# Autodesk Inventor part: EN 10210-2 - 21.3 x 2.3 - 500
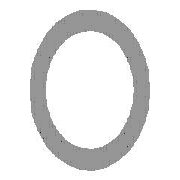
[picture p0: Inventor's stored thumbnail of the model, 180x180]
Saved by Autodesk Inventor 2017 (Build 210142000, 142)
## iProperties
Created: 2016-02
Part Number: EN 10210-2 - 21.3 x 2.3 - 500
Material: Steel, Mild
Description: Pipe
Document SubType Name: Modeling
Standard: DIN
Designer: iusti
Standard Revision: 2006-07
Standards Organization: DIN
Language: en-US
Size Designation: 21.3 x 2.3
Categories: <MemberInstance><Categories><Category DisplayName="Structural Shapes" InternalName="089c4875-fa83-4c05-b084-43b9cc11f5ed" Mnemonic="GRDR"><CategoryParameter Dis
Stock Number: 21.3 x 2.3
Density: 7.85 g/cm^3
Appearance: Semi-Polished
_CCFamilyMember: 1
_CCFamilyDisplayName: DIN EN 10210-2 - Pipe
_FrameMemberDoc: Frame Member File
_Version: 15.0.0
_GetPNFromCC: 1
IsCustomPart: 1
Author: iusti
G_L: 500.000 mm
G_W: 21.300 mm
G_H: 21.300 mm
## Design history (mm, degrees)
node "Start plane"
node "End plane"
sketch "Sketch"
  geometry: C1 r 8.35 at (0, 0); C2 r 10.65 at (0, 0); 2 further points
  constraints: 3 coincident, 2 centre point
  dimensions: "d0" = 21.3 diameter of C2 (= G_H); "d1" = 2.3 radial gap between concentric circles of C2 C1 (= G_T)
extrude "Body" new body sketch "Sketch" stored distance "d2" = 500 (= G_L); taper "d3" = 0 deg
node "Driven Length"
  sketch "Sketch3"
    geometry: L1 (0, 0)-(10, 0) reference
    constraints: 2 end point, 1 horizontal
  workplane "Work Plane3"
  sketch "Sketch4"
    geometry: L1 (-2, 0)-(12, 0) reference; L2 (-2, 500)-(12, 500) reference
    dimensions: "d7" = 500 distance between parallel lines of L1 L2 (derived)
body "Solid1"
other parameters: "G_H" = 21.3 [user parameter; used in 1 equation term], "G_T" = 2.3 [user parameter; used in 1 equation term], "G_L" = 500 (= d7) [user parameter; used in 1 equation term], "G_OFFSET_START" = 0 [user parameter; used in 1 equation term], "G_OFFSET_END" = 0 [user parameter; used in 1 equation term], "d4" = 0 (computed from G_OFFSET_START), "d6" = 90 deg
